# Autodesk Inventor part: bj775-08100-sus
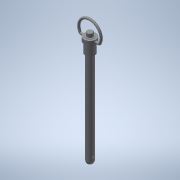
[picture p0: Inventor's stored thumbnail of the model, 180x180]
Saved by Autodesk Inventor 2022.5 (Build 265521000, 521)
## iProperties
Created: 2016-12
Part Number: bj775-08100-sus
Material: 一般
Document SubType Name: Modeling
Designer: imaocorp
Density: 1 g/cm^3
Appearance: 既定
Author: imaocorp
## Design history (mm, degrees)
node "bj775-08100-sus.x_t1"
node "bj775-08100-sus"
node "Base1"
